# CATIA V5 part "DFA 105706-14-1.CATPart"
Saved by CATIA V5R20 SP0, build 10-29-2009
Part number: DFA 105706-14-1
Revision: ANY
Definition: UNKNOWN
Nomenclature: DFA 105706-14-1
Source: Unknown
Bounding box of the stored display mesh (mm): x -5 to 5, y -10 to 10, z -5 to 5
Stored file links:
  C:\Users\Utente\Desktop\IO LAVORO\3D X SITO CF\CUMSA\3D files FA\FA 105706-21\DFA 105706-14-1.CATPart
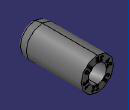
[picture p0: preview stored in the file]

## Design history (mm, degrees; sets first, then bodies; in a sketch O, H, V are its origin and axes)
Body1 "Cortar-Extruir5" (main body)
  Solid1: solid without history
